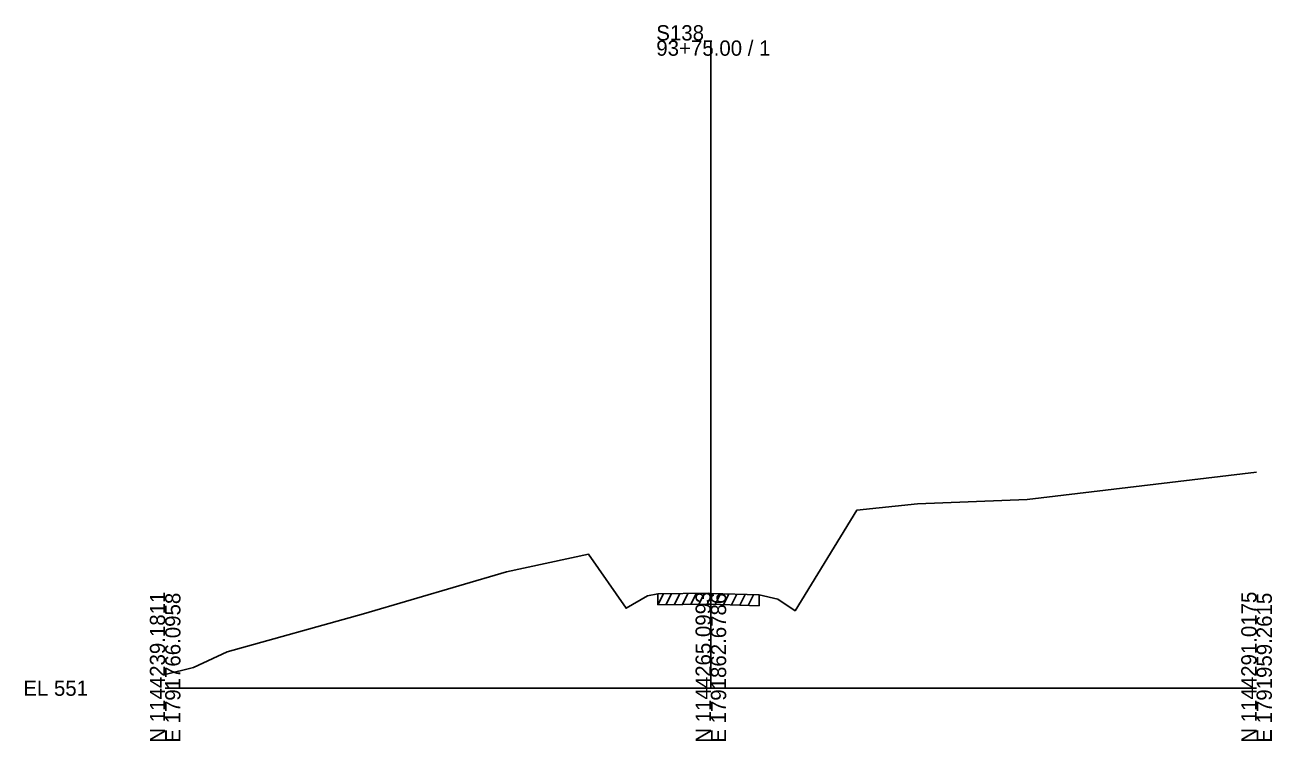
# Model space of a CAD drawing. Extents: x -26 to 1203, y -10 to 19606.
# Drawn here: x 974.3 to 1202.8, y 7490.3 to 7621.5 of the extents above; entities that cross this region are included whole.
import ezdxf

# ---------------------------------------------------------------- set-up
doc = ezdxf.new("R2010")
doc.units = 0
for name, color, linetype in [('RD_EX_Driveway', 7, 'Continuous'), ('RD_GPK_XS_Cell', 7, 'Continuous'), ('RD_XS_ExGround', 7, 'Continuous'), ('RD_XS_ExPaveRet', 7, 'Continuous')]:
    doc.layers.add(name, color=color, linetype=linetype)

msp = doc.modelspace()

# ---------------------------------------------------------------- linework, layer by layer
at = {"layer": 'RD_GPK_XS_Cell'}
for p, q in [((1100, 7500), (1100, 7618.7)), ((1000, 7500), (1100, 7500)), ((1100, 7500), (1200, 7500))]:
    msp.add_line(p, q, dxfattribs=at)
at = {"layer": 'RD_XS_ExGround'}
msp.add_lwpolyline([(1000, 7502.52), (1005.22, 7503.76), (1011.34, 7506.66), (1036.36, 7513.65), (1062.58, 7521.33), (1077.59, 7524.54), (1084.46, 7514.66), (1088.36, 7516.91), (1090.31, 7517.3), (1099.51, 7517.38), (1100, 7517.37), (1108.83, 7517.1), (1112.29, 7516.34), (1115.44, 7514.18), (1126.76, 7532.65), (1137.88, 7533.8), (1157.97, 7534.57), (1200, 7539.57)], dxfattribs=at)
at = {"layer": 'RD_XS_ExPaveRet'}
for p, q in [((1090.31, 7515.3), (1091.31, 7517.31)), ((1090.31, 7515.3), (1090.31, 7517.3)), ((1091.81, 7515.32), (1092.81, 7517.33)), ((1093.31, 7515.33), (1094.31, 7517.34)), ((1094.81, 7515.34), (1095.81, 7517.35)), ((1096.31, 7515.36), (1097.31, 7517.37)), ((1097.81, 7515.37), (1098.81, 7517.38)), ((1099.31, 7515.38), (1100.3, 7517.36)), ((1100.81, 7515.34), (1101.79, 7517.31)), ((1102.31, 7515.3), (1103.29, 7517.27)), ((1103.81, 7515.25), (1104.79, 7517.22)), ((1105.31, 7515.2), (1106.29, 7517.17)), ((1106.81, 7515.16), (1107.79, 7517.13)), ((1108.83, 7517.1), (1108.83, 7515.1)), ((1090.31, 7515.3), (1099.51, 7515.38)), ((1099.51, 7515.38), (1100, 7515.37)), ((1100, 7515.37), (1108.83, 7515.1))]:
    msp.add_line(p, q, dxfattribs=at)

# ---------------------------------------------------------------- texts
at = {"layer": 'RD_EX_Driveway'}
msp.add_text('559.68', height=0.0975, rotation=90, dxfattribs=at).set_placement((1100.1, 7517.37))
at = {"layer": 'RD_GPK_XS_Cell'}
for s, p in [('S138', (1090, 7618.7)), ('93+75.00 / 1', (1090, 7615.9)), ('EL 551', (974, 7498.6))]:
    msp.add_text(s, height=2.8, dxfattribs=at).set_placement(p)
for s, p in [('N 1144239.1811', (1000, 7490)), ('E 1791766.0958', (1002.8, 7490)), ('N 1144265.0993', (1100, 7490)), ('E 1791862.6786', (1102.8, 7490)), ('N 1144291.0175', (1200, 7490)), ('E 1791959.2615', (1202.8, 7490))]:
    msp.add_text(s, height=2.8, rotation=90, dxfattribs=at).set_placement(p)

doc.saveas('drawing.dxf')
